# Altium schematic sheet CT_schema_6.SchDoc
size 274 x 160 mm
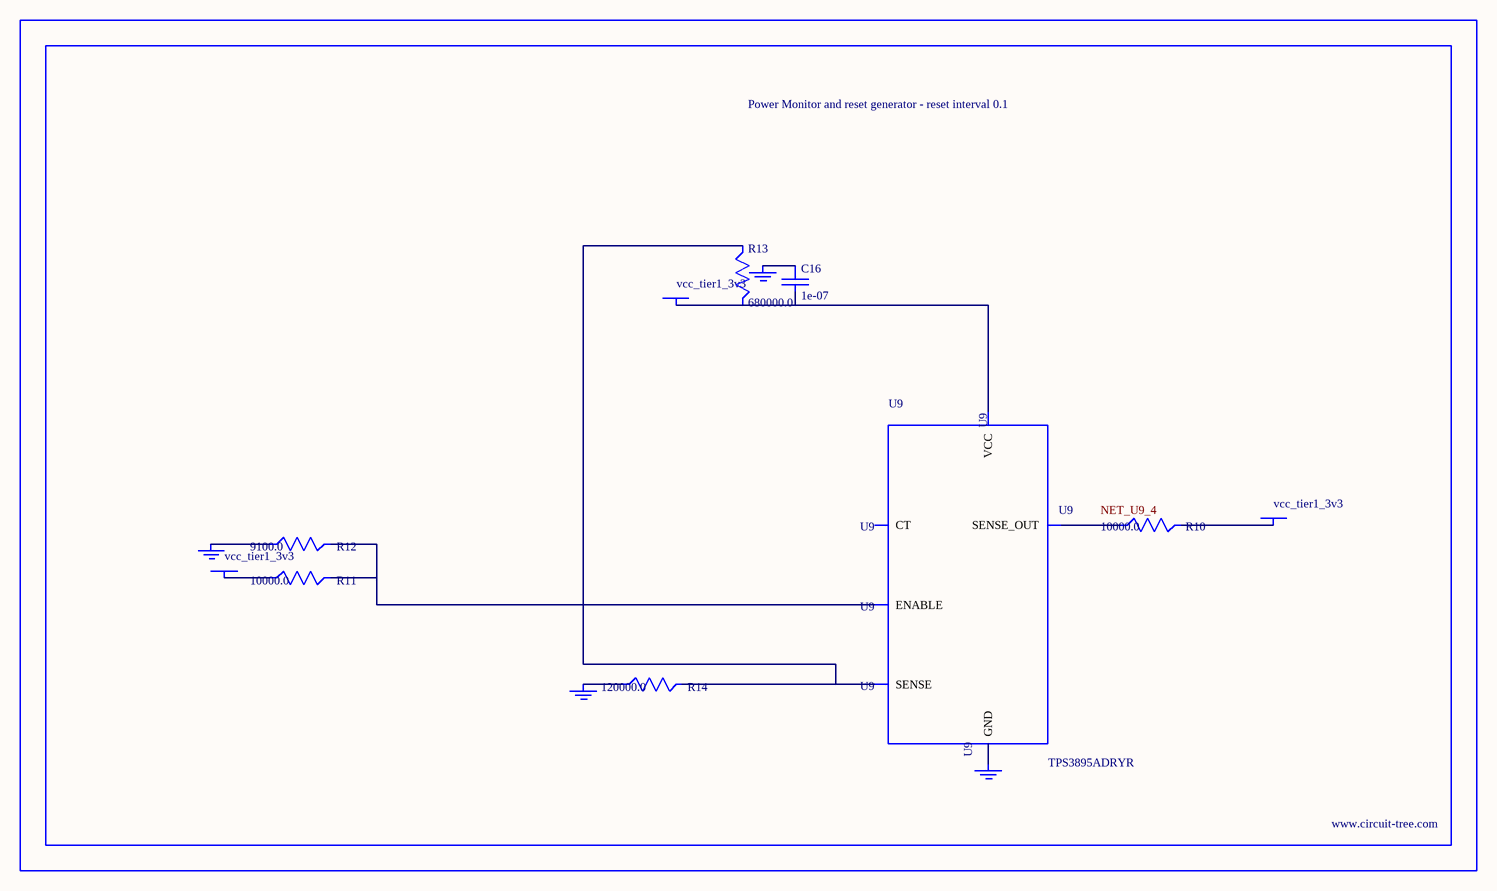
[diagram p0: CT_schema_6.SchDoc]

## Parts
BORDER5  (no value)
C16  1e-07  [C0402]
GND_INSTANCE_5_0  (no value)
GND_INSTANCE_5_1  (no value)
GND_INSTANCE_5_2  (no value)
GND_INSTANCE_5_3  (no value)
POWER_INSTANCE_5_0  vcc_tier1_3v3
POWER_INSTANCE_5_1  vcc_tier1_3v3
POWER_INSTANCE_5_2  vcc_tier1_3v3
R10  10000.0  [R0603]
R11  10000.0  [R0603]
R12  9100.0  [R0603]
R13  680000.0  [R0603]
R14  120000.0  [R0603]
U9  TPS3895ADRYR  [SON-6]

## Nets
NetC16_1: C16.1 GND_INSTANCE_5_2.0(GND)
NetC16_2: C16.2 POWER_INSTANCE_5_2.0(PWR) R13.2 U9.6(VCC)
NetGND_INSTANCE_5_0_0: GND_INSTANCE_5_0.0(GND) R12.1
NetGND_INSTANCE_5_1_0: GND_INSTANCE_5_1.0(GND) R14.1
NetGND_INSTANCE_5_3_0: GND_INSTANCE_5_3.0(GND) U9.2(GND)
NetPOWER_INSTANCE_5_0_0: POWER_INSTANCE_5_0.0(PWR) R11.1
NetPOWER_INSTANCE_5_1_0: POWER_INSTANCE_5_1.0(PWR) R10.2
NetR10_1: R10.1 U9.4(SENSE_OUT)
NetR11_2: R11.2 R12.2 U9.1(ENABLE)
NetR13_1: R13.1 R14.2 U9.3(SENSE)

Not connected (* = marked no-connect by the designer): U9 5(CT)

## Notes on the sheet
- Labels drawn without touching a wire or pin: NET_U9_4

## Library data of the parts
BORDER5 = BORDER_PAGE5
C16 = C0402C104K3RACTU
GND_INSTANCE_5_0-GND_INSTANCE_5_3 = GND
POWER_INSTANCE_5_0-POWER_INSTANCE_5_2 = PWR
R10 R11 = RC0603JR-0710KL
R12 = RC0603JR-079K1L
R13 = RC0603JR-07680KL
R14 = RC0603JR-07120KL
